Omron CX-Programmer project NuevoProyecto (CX-Programmer 9.50)

# PLC NewPLC1: CQM1 CPU21

## Program P6_1 (no task)
Local symbols
Etapa_0 10.00 BOOL
Etapa_1 10.01 BOOL
Etapa_2 10.02 BOOL
Etapa_3 10.03 BOOL
Etapa_4 10.04 BOOL
Etapa_5 10.05 BOOL
Etapa_6 10.06 BOOL
Etapa_7 10.07 BOOL
F1 0.04 BOOL
F2 0.05 BOOL
FB 0.03 BOOL
FCP 0.06 BOOL
KB 100.01 BOOL
KS 100.00 BOOL
P1 0.01 BOOL
P2 0.02 BOOL
PB 0.00 BOOL
T_0 15.00 BOOL

### Section Sección1_Programa_principal
; Programa principal (Etapas 0 ... 7)

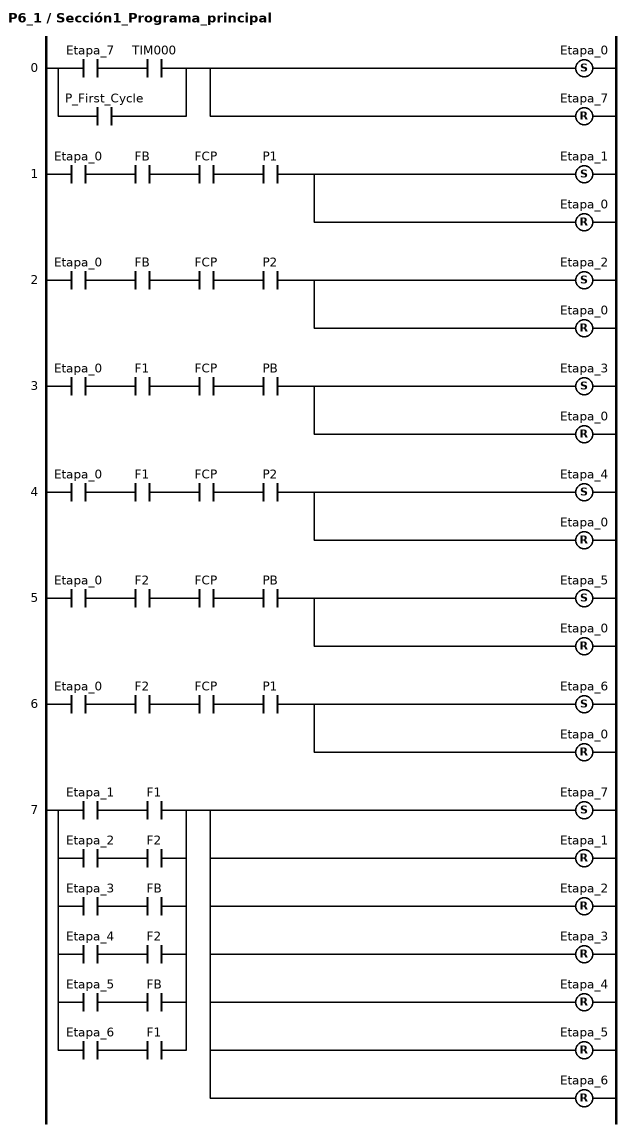
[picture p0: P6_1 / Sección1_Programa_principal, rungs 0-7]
; rung 0
LD Etapa_7
AND TIM000
OR P_First_Cycle
SET Etapa_0
RSET Etapa_7
; rung 1
LD Etapa_0
AND FB
AND FCP
AND P1
SET Etapa_1
RSET Etapa_0
; rung 2
LD Etapa_0
AND FB
AND FCP
AND P2
SET Etapa_2
RSET Etapa_0
; rung 3
LD Etapa_0
AND F1
AND FCP
AND PB
SET Etapa_3
RSET Etapa_0
; rung 4
LD Etapa_0
AND F1
AND FCP
AND P2
SET Etapa_4
RSET Etapa_0
; rung 5
LD Etapa_0
AND F2
AND FCP
AND PB
SET Etapa_5
RSET Etapa_0
; rung 6
LD Etapa_0
AND F2
AND FCP
AND P1
SET Etapa_6
RSET Etapa_0
; rung 7
LD Etapa_1
AND F1
LD Etapa_2
AND F2
ORLD
LD Etapa_3
AND FB
ORLD
LD Etapa_4
AND F2
ORLD
LD Etapa_5
AND FB
ORLD
LD Etapa_6
AND F1
ORLD
SET Etapa_7
RSET Etapa_1
RSET Etapa_2
RSET Etapa_3
RSET Etapa_4
RSET Etapa_5
RSET Etapa_6

### Section Sección2_Temporizador

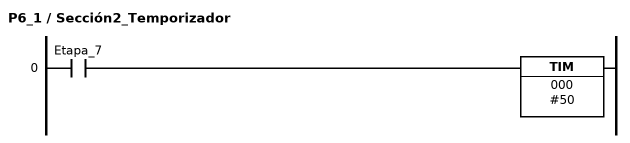
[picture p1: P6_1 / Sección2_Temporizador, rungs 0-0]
; rung 0
LD Etapa_7
TIM 000 #50

### Section Sección3_Salidas

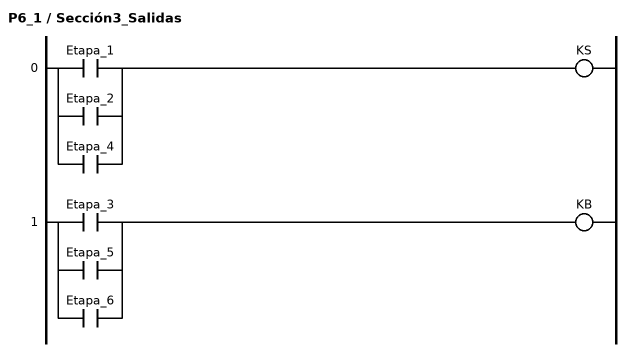
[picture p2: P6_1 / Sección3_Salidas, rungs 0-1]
; rung 0
LD Etapa_1
OR Etapa_2
OR Etapa_4
OUT KS
; rung 1
LD Etapa_3
OR Etapa_5
OR Etapa_6
OUT KB

### Section Sección4_END
; rung 0: Fin de programa
END(01)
